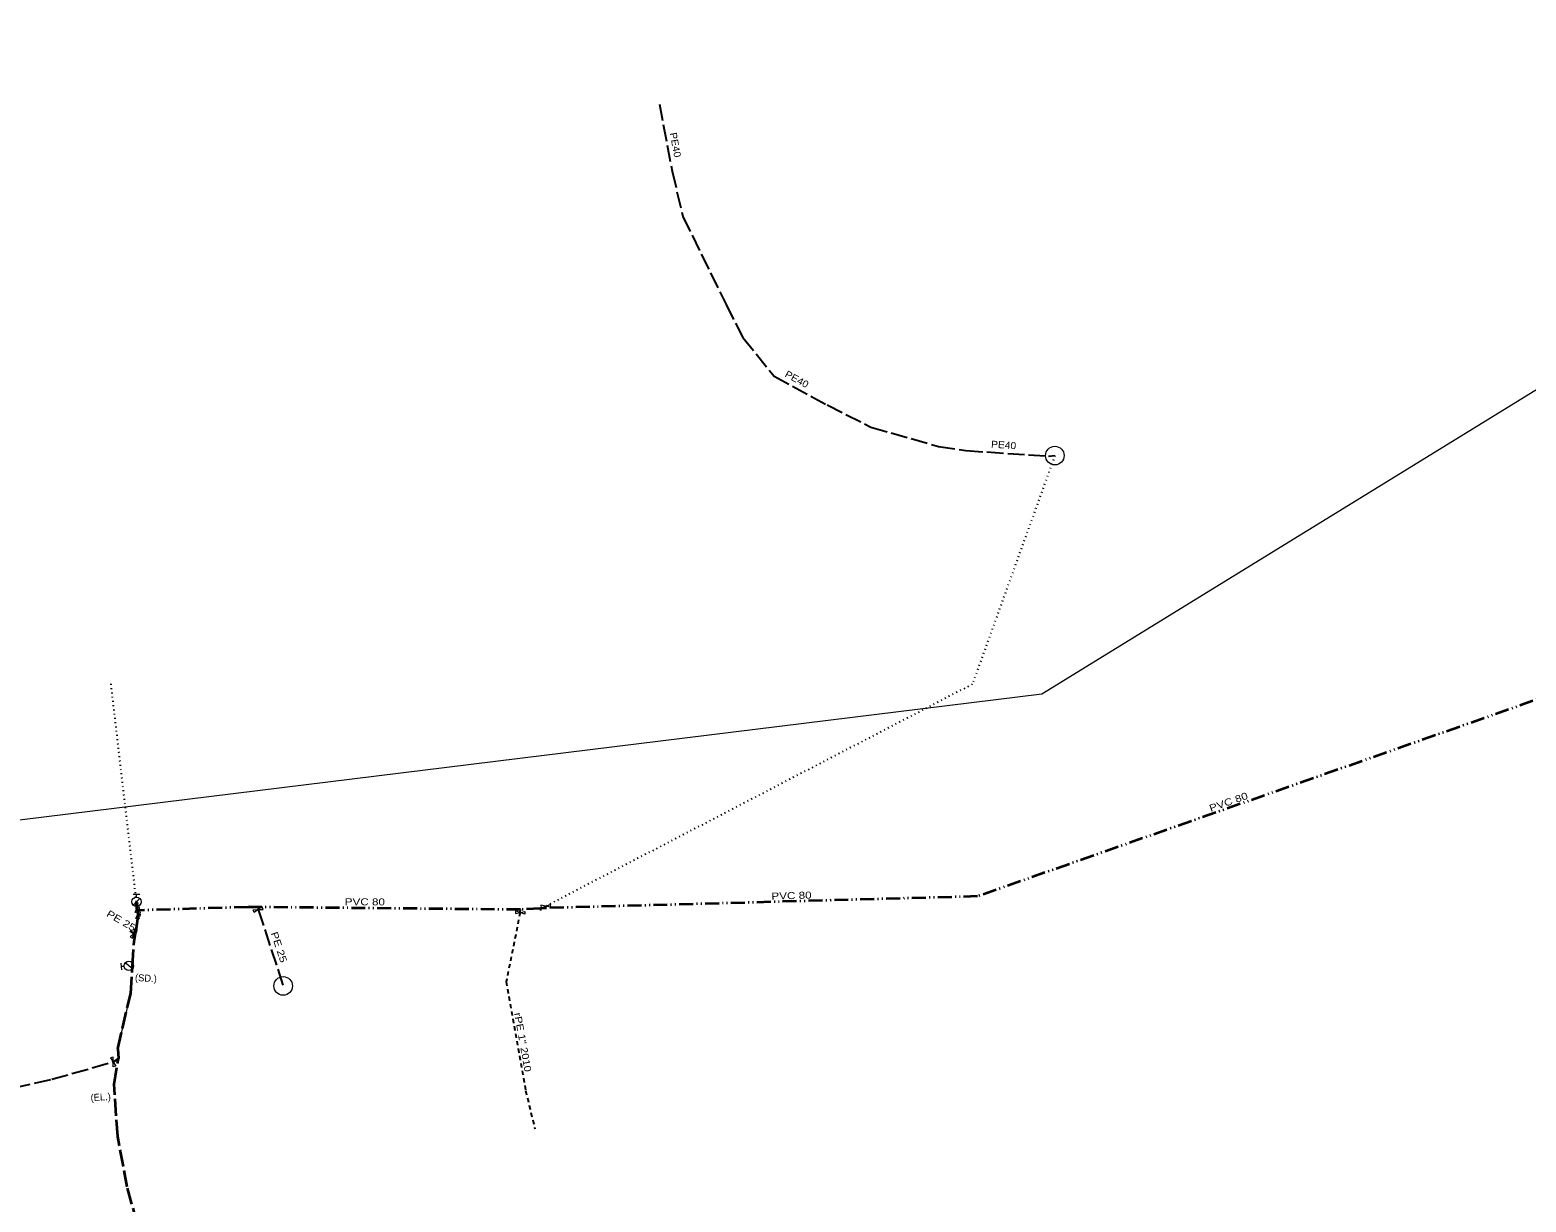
# Model space of a CAD drawing. Extents: x -582626 to -580899, y -1097611 to -1096610.
# Drawn here: x -581940.6 to -581779.8, y -1097164.8 to -1097038.9 of the extents above; entities that cross this region are included whole.
import ezdxf
from ezdxf.enums import TextEntityAlignment as Align

# ---------------------------------------------------------------- set-up
doc = ezdxf.new("R2010")
doc.units = 0
doc.header["$LTSCALE"] = 0.3
for name, pattern in [('DASH_DOUBLE_DOT', [9.2, 5, -1.2, 0.3, -1.2, 0.3, -1.2]), ('DOTTED', [1.5, 0.3, -1.2]), ('LONG_DASHED', [7.5, 6, -1.5]), ('SHORT_DASHED', [2.7, 1.5, -1.2])]:
    doc.linetypes.add(name, pattern=pattern)
for name, color, linetype, lineweight in [('1', 7, 'Continuous', 13), ('10', 7, 'Continuous', 13), ('25', 7, 'Continuous', 13), ('35', 7, 'LONG_DASHED', 35), ('36', 7, 'DASH_DOUBLE_DOT', 35), ('50', 7, 'LONG_DASHED', 25), ('51', 7, 'DOTTED', 25)]:
    doc.layers.add(name, color=color, linetype=linetype, lineweight=lineweight)
doc.layers.add('16', color=7, linetype='Continuous')
doc.layers.add('19', color=7, linetype='Continuous')

msp = doc.modelspace()

# ---------------------------------------------------------------- linework, layer by layer
at = {"layer": '1'}
msp.add_lwpolyline([(-582625.57, -1097394.66), (-582612.34, -1097467.421), (-582321.299, -1097262.369), (-581897.965, -1097202.837), (-581719.372, -1097182.994), (-581593.695, -1097110.233), (-581382.028, -1096971.327), (-581362.184, -1096819.192), (-581322.497, -1096739.817), (-581210.049, -1096733.202), (-581097.601, -1096686.9), (-580905.778, -1096719.973), (-580899.163, -1096627.369), (-581084.372, -1096614.14), (-581216.663, -1096680.285), (-581368.799, -1096686.9), (-581434.945, -1096812.577), (-581468.018, -1096971.327), (-581659.84, -1097004.4), (-581831.82, -1097110.233), (-582314.684, -1097169.765), (-582519.736, -1097295.442), (-582625.57, -1097394.66)], close=True, dxfattribs=at)
at = {"layer": '10'}
for p, q in [((-581929.493, -1097132.907), (-581928.786, -1097132.2)), ((-581929.489, -1097131.753), (-581928.789, -1097131.753)), ((-581929.139, -1097132.053), (-581929.139, -1097131.753)), ((-581928.86, -1097133.185), (-581928.872, -1097132.935)), ((-581928.744, -1097133.902), (-581928.723, -1097133.652)), ((-581930.725, -1097139.871), (-581930.785, -1097139.174)), ((-581930.456, -1097139.497), (-581930.755, -1097139.522)), ((-581929.575, -1097139.776), (-581930.34, -1097139.132))]:
    msp.add_line(p, q, dxfattribs=at)
for points in [[(-581929.11, -1097133.196), (-581928.901, -1097133.687), (-581929.274, -1097133.704), (-581929.11, -1097133.196), (-581928.946, -1097132.688), (-581929.319, -1097132.705), (-581929.11, -1097133.196), (-581928.86, -1097133.185), (-581928.849, -1097133.434)], [(-581928.993, -1097133.881), (-581928.848, -1097134.395), (-581929.22, -1097134.364), (-581928.993, -1097133.881), (-581928.766, -1097133.398), (-581929.138, -1097133.367), (-581928.993, -1097133.881), (-581928.744, -1097133.902), (-581928.764, -1097134.151)]]:
    msp.add_lwpolyline(points, dxfattribs=at)
for points in [[(-581916.062, -1097133.397), (-581916.49, -1097133.695), (-581916.584, -1097133.41), (-581916.062, -1097133.397), (-581915.54, -1097133.384), (-581915.634, -1097133.099)], [(-581887.903, -1097133.704), (-581887.393, -1097133.592), (-581887.416, -1097133.891), (-581887.903, -1097133.704), (-581888.39, -1097133.517), (-581888.413, -1097133.816)], [(-581885.155, -1097133.04), (-581884.667, -1097132.853), (-581884.645, -1097133.153), (-581885.155, -1097133.04), (-581885.665, -1097132.927), (-581885.643, -1097133.227)], [(-581929.435, -1097135.962), (-581929.313, -1097135.454), (-581929.054, -1097135.605), (-581929.435, -1097135.962), (-581929.816, -1097136.319), (-581929.557, -1097136.47)], [(-581931.652, -1097149.768), (-581931.371, -1097150.208), (-581931.66, -1097150.29), (-581931.652, -1097149.768), (-581931.644, -1097149.246), (-581931.933, -1097149.328)]]:
    msp.add_lwpolyline(points, close=True, dxfattribs=at)
for centre, radius in [((-581830.441, -1097084.611), 1), ((-581929.1388, -1097132.5527), 0.5), ((-581929.9583, -1097139.4538), 0.5), ((-581913.374, -1097141.603), 1)]:
    msp.add_circle(centre, radius, dxfattribs=at)
at = {"layer": '25'}
msp.add_line((-581931.157, -1097148.353), (-581929.763, -1097142.417), dxfattribs=at)
at = {"layer": '35'}
for p, q in [((-581929.11, -1097133.196), (-581929.139, -1097132.553)), ((-581929.064, -1097133.453), (-581929.11, -1097133.196)), ((-581929.064, -1097133.453), (-581928.993, -1097133.881)), ((-581929.064, -1097133.453), (-581928.84, -1097133.484)), ((-581931.157, -1097148.353), (-581929.763, -1097142.417)), ((-581931.157, -1097148.353), (-581931.077, -1097149.404))]:
    msp.add_line(p, q, dxfattribs=at)
for points in [[(-581928.993, -1097133.881), (-581929.036, -1097134.402), (-581929.231, -1097135.958)], [(-581929.763, -1097142.417), (-581929.568, -1097139.466), (-581929.384, -1097136.816), (-581929.231, -1097135.958)], [(-581923.124, -1097181.605), (-581923.656, -1097180.992), (-581925.99, -1097176.415), (-581928.438, -1097169.399), (-581930.127, -1097163.204), (-581931.156, -1097157.791), (-581931.542, -1097152.159), (-581931.077, -1097149.404)]]:
    msp.add_lwpolyline(points, dxfattribs=at)
at = {"layer": '36'}
for p, q in [((-581773.803, -1097109.134), (-581838.74, -1097131.974)), ((-581838.74, -1097131.974), (-581885.135, -1097133.239)), ((-581917.149, -1097133.121), (-581928.84, -1097133.484))]:
    msp.add_line(p, q, dxfattribs=at)
at = {"layer": '36', "linetype": 'DOTTED'}
msp.add_line((-581929.568, -1097139.466), (-581929.958, -1097139.454), dxfattribs=at)
at = {"layer": '36'}
msp.add_lwpolyline([(-581885.135, -1097133.239), (-581885.728, -1097133.288), (-581887.867, -1097133.405), (-581917.149, -1097133.121)], dxfattribs=at)
at = {"layer": '50'}
for p, q in [((-581863.968, -1097071.923), (-581860.611, -1097076.074)), ((-581916.092, -1097133.289), (-581916.062, -1097133.397)), ((-581916.062, -1097133.397), (-581913.374, -1097141.603)), ((-581929.435, -1097135.962), (-581929.835, -1097135.729)), ((-581929.231, -1097135.958), (-581929.435, -1097135.962))]:
    msp.add_line(p, q, dxfattribs=at)
for points in [[(-581872.933, -1097046.825), (-581871.566, -1097054.059), (-581870.418, -1097058.916), (-581865.78, -1097068.364), (-581863.968, -1097071.923)], [(-581860.611, -1097076.074), (-581854.894, -1097079.169), (-581850.196, -1097081.54), (-581842.954, -1097083.624)], [(-581842.954, -1097083.624), (-581839.988, -1097084.065), (-581831.123, -1097084.671), (-581830.441, -1097084.611)], [(-581969.433, -1097162.839), (-581969.118, -1097162.432), (-581968.746, -1097157.885), (-581968.147, -1097157.152), (-581957.136, -1097155.212), (-581946.694, -1097153.55), (-581938.237, -1097151.64), (-581931.652, -1097149.768)], [(-581931.652, -1097149.768), (-581931.579, -1097149.71), (-581931.077, -1097149.404)]]:
    msp.add_lwpolyline(points, dxfattribs=at)
at = {"layer": '51'}
for p, q in [((-581929.139, -1097132.553), (-581931.891, -1097109.001)), ((-581885.155, -1097133.04), (-581885.135, -1097133.239))]:
    msp.add_line(p, q, dxfattribs=at)
at = {"layer": '51', "linetype": 'SHORT_DASHED'}
msp.add_line((-581887.903, -1097133.704), (-581887.867, -1097133.405), dxfattribs=at)
at = {"layer": '51', "linetype": 'DASH_DOUBLE_DOT'}
msp.add_line((-581885.728, -1097133.288), (-581885.711, -1097133.498), dxfattribs=at)
at = {"layer": '51'}
msp.add_lwpolyline([(-581830.441, -1097084.611), (-581839.312, -1097109.188), (-581885.155, -1097133.04)], dxfattribs=at)
at = {"layer": '51', "linetype": 'SHORT_DASHED'}
msp.add_lwpolyline([(-581887.903, -1097133.704), (-581889.414, -1097141.16), (-581887.312, -1097152.856), (-581886.327, -1097156.945)], dxfattribs=at)

# ---------------------------------------------------------------- texts
at = {"layer": '16', "width": 1.25}
for rotation, p in [(19.378, (-581811.6474, -1097122.1797)), (359.695, (-581904.598, -1097132.9377)), (1.562, (-581858.7292, -1097132.2692))]:
    msp.add_text('PVC 80', height=0.75, rotation=rotation, dxfattribs=at).set_placement(p, align=Align.CENTER)
at = {"layer": '16'}
for s, rotation, p in [('(SD.)', 356.56, (-581928.1455, -1097141.1324)), ('(EL.)', 3.097, (-581932.9663, -1097153.9201))]:
    msp.add_text(s, height=0.75, rotation=rotation, dxfattribs=at).set_placement(p, align=Align.CENTER)
at = {"layer": '19'}
for s, rotation, width, p in [('PE40', 280.701, 1.1, (-581871.5812, -1097051.2864)), ('PE40', 280.701, 1.1, (-581871.5812, -1097051.2864)), ('PE40', 331.57, 1.1, (-581858.342, -1097076.734)), ('PE40', 331.57, 1.1, (-581858.342, -1097076.734)), ('PE40', 356.089, 1.1, (-581835.9626, -1097083.8387)), ('PE40', 356.089, 1.1, (-581835.9626, -1097083.8387)), ('PE 25', 329.779, 1.25, (-581930.9618, -1097134.9184)), ('PE 25', 288.137, 1.25, (-581914.1771, -1097137.5468)), ('rPE 1" 2010', 280.188, 1.2, (-581887.9816, -1097147.7172))]:
    msp.add_text(s, height=0.75, rotation=rotation, dxfattribs=dict(at, width=width)).set_placement(p, align=Align.CENTER)

doc.saveas('drawing.dxf')
